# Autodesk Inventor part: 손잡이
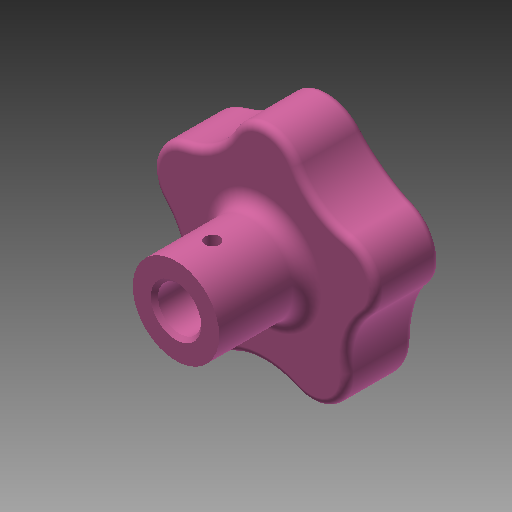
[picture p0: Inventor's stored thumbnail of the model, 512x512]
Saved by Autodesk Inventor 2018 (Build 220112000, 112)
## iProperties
Created: 2020-03
Part Number: 손잡이
Material: 알루미늄 6061
Document SubType Name: Modeling
Designer: mduedu
Density: 2.71 g/cm^3
Appearance: 분홍색
Mass: 19.3677 g
Surface Area: 28.5052 cm^2
Volume: 7.14675 cm^3
Author: mduedu
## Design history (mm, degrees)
sketch "스케치1" dims "d1" = 22
  geometry: C1 r 16 at (0, 0); C2 r 5 at (0, 11); C3 r 5 at (-10.462, 3.399); C4 r 5 at (-6.466, -8.899); C5 r 5 at (6.466, -8.899); C6 r 5 at (10.462, 3.399); 2 further points
  constraints: 6 centre point, 2 coincident, 2 vertical alignment, 1 tangent, 13 other
  dimensions: "d0" = 32 diameter of C1; "d4" = 360 deg dimension on point (0, 0) C2.centre (derived); "d6" = 10 diameter of C2 (derived)
extrude "돌출1" new body sketch "스케치1" distance "d8" = 10; taper "d9" = 0 deg
fillet "모깎기1" dims "d10" = 10
fillet "모깎기2" dims "d11" = 10
fillet "모깎기3" dims "d12" = 10
fillet "모깎기4" dims "d13" = 10
fillet "모깎기5" dims "d14" = 10
sketch "스케치2"
  geometry: L1 (16, 10)-(16, 0) reference; L2 (16, 0)-(-12.434, 0) reference; L3 (-12.434, 0)-(-12.434, 10) reference; L4 (-12.434, 10)-(16, 10) reference; L5 (10.5, 0)-(16, 1.169); L6 (16, 1.169)-(16, 0); L7 (16, 0)-(10.5, 0); L8 (0, 0)-(0, 10)
  constraints: 8 end point, 3 perpendicular, 3 point on line
  dimensions: "d15" = 5.5 distance of L5.start L1.end; "d16" = 12 deg angle of L2 L5
revolve "회전1" sketch "스케치2" stored, may be unused: angle "d17" = 90 deg
fillet "모깎기6" dims "d18" = 1
sketch "스케치3"
  geometry: C1 r 6 at (0, 0); 1 further point
  constraints: 1 centre point, 1 coincident
  dimensions: "d19" = 12 diameter of C1
extrude "돌출2" join sketch "스케치3" distance "d20" = 12.2; taper "d21" = 0 deg
fillet "모깎기7" dims "d22" = 2
hole "구멍1" diameter "d25" = 6; stored, may be unused: countersink angle "d29" = 90 deg, drill point angle "d31" = 118 deg; dims "d23" = 10, "d24" = 10, "d26" = 6, "d27" = 4, "d28" = 2, "d30" = 15
sketch "스케치4"
  geometry: L1 (6, 22.2)-(-6, 22.2) reference; C1 r 1 at (0, 17.2); 1 further point
  constraints: 1 centre point, 1 vertical alignment
  dimensions: "d32" = 2 diameter of C1; "d34" = 5 distance from line of C1.centre L1
extrude "돌출3" cut sketch "스케치4" extent not by distance; stored distance "d35" = 12.2; taper "d36" = 0 deg
chamfer "모따기2" distance "d40" = 0.5; stored, may be unused: second distance "d41" = 2, angle "d42" = 45 deg
node "솔리드1"
node "절단 모서리 투영1"
